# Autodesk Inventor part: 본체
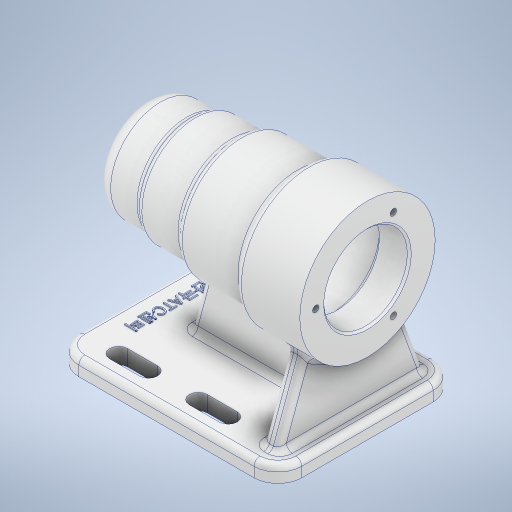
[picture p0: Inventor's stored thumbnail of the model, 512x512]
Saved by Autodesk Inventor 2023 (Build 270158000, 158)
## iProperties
Created: 2022-07
Part Number: 본체
Material: 알루미늄 6061
Document SubType Name: Modeling
Designer: owner
Density: 2.7 g/cm^3
Appearance: 알루미늄 - 평지
Mass: 693.1 g
Surface Area: 698.776 cm^2
Volume: 256.704 cm^3
Author: owner
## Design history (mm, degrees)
sketch "스케치1"
  geometry: L1 (44, -45)-(-44, -45); L2 (-56, -33)-(-56, 33); L3 (-44, 45)-(44, 45); L4 (56, 33)-(56, -33); L5 (56, -45)-(-56, 45); L6 (-56, -45)-(56, 45); A1 r 12 centre (44, 33) between (56, 33) and (44, 45); A2 r 12 centre (44, -33) between (44, -45) and (56, -33); A3 r 12 centre (-44, -33) between (-56, -33) and (-44, -45); A4 r 12 centre (-44, 33) between (-44, 45) and (-56, 33); 1 further point
  constraints: 12 end point, 8 point on circle, 8 point on line, 8 tangent, 4 centre point, 3 equal radius, 2 midpoint, 2 parallel, 1 horizontal, 1 perpendicular
  dimensions: "d0" = 112 distance between parallel lines of L2 L4; "d1" = 90 distance of L6.start L5.end; "d4" = 12 radius of A1
extrude "돌출1" new body sketch "스케치1" distance "d2" = 8; taper "d3" = 0 deg
sketch "스케치2"
  geometry: L1 (-36, -33)-(-21, -33); L2 (-36, -37.5)-(-21, -37.5); L3 (-21, -28.5)-(-36, -28.5); L4 (-56, 33)-(-56, -33) reference; L5 (-44, -45)-(44, -45) reference; L6 (19, -28.5)-(4, -28.5); L7 (4, -37.5)-(19, -37.5); L8 (-21, 37.5)-(-36, 37.5); L9 (-36, 28.5)-(-21, 28.5); L10 (19, 37.5)-(4, 37.5); L11 (4, 28.5)-(19, 28.5); A1 r 4.5 centre (-36, -33) between (-36, -28.5) and (-36, -37.5); A2 r 4.5 centre (-21, -33) between (-21, -37.5) and (-21, -28.5); A3 r 4.5 centre (19, -33) between (19, -37.5) and (19, -28.5); A4 r 4.5 centre (4, -33) between (4, -28.5) and (4, -37.5); A5 r 4.5 centre (-21, 33) between (-21, 28.5) and (-21, 37.5); A6 r 4.5 centre (-36, 33) between (-36, 37.5) and (-36, 28.5); A7 r 4.5 centre (19, 33) between (19, 28.5) and (19, 37.5); A8 r 4.5 centre (4, 33) between (4, 37.5) and (4, 28.5); 2 further points
  constraints: 20 end point, 16 point on circle, 8 centre point, 4 tangent, 2 horizontal, 1 midpoint, 1 parallel, 1 vertical, 30 other
  dimensions: "d5" = 15 distance of L1.start L1.end; "d6" = 9 diameter of A2; "d7" = 20 distance from line of L1.start L4; "d8" = 33 distance from line of L1 point (0, 0); "d11" = 40 distance of L1.end A3.centre; "d14" = 66 distance of L1.end A5.centre
extrude "돌출2" cut sketch "스케치2" stored distance "d17" = 8; taper "d18" = 0 deg
fillet "모깎기1" dims "d19" = 3
sketch "스케치3"
  geometry: L1 (-56, 33)-(-56, -33) reference; 2 further points
  constraints: 1 horizontal alignment, 1 other
  dimensions: "d20" = 12 distance from line of point (-44, 0) L1
feature "엠보싱1" sketch "스케치3" dims "d0" = 112, "d1" = 90, "d4" = 12, "d21" = 0.5, "d22" = 0
sketch "스케치4"
  geometry: L1 (-56, 70)-(56, 70); L2 (-44, 0)-(44, 0) reference; L3 (-47, 80.5)-(-47, 85.7); L4 (-46.7, 86)-(-43, 86); L5 (-43, 86)-(-43, 87.2); L6 (-42.7, 87.5)-(-25, 87.5); L7 (-25, 87.5)-(-25, 90.7); L8 (-24.7, 91)-(-13, 91); L9 (-13, 91)-(-13, 91); L10 (-10, 94)-(38, 94); L11 (41, 91)-(41, 91); L12 (41, 91)-(55, 91); L13 (56, 104)-(56, 92); L14 (-56, 87)-(-56, 70); L15 (-48, 95)-(-32, 95); L16 (-32, 95)-(-32, 97); L17 (-32, 97)-(-10, 97); L18 (-10, 97)-(-10, 100); L19 (-10, 100)-(24, 100); L20 (24, 100)-(24, 104); L21 (24, 104)-(56, 104); L22 (-47, 80.5)-(-47, 80.5); L23 (-50, 77.5)-(-50, 70); L24 (56, 0)-(56, 5) reference; L25 (55, 91)-(56, 92); A1 r 8 centre (-48, 87) between (-48, 95) and (-56, 87); A2 r 3 centre (-47, 77.5) between (-47, 80.5) and (-50, 77.5); A3 r 3 centre (-10, 91) between (-10, 94) and (-13, 91); A4 r 3 centre (38, 91) between (41, 91) and (38, 94); A5 r 0.3 centre (-46.7, 85.7) between (-46.7, 86) and (-47, 85.7); A6 r 0.3 centre (-42.7, 87.2) between (-42.7, 87.5) and (-43, 87.2); A7 r 0.3 centre (-24.7, 90.7) between (-24.7, 91) and (-25, 90.7); 7 further points
  constraints: 46 end point, 17 perpendicular, 14 point on circle, 14 tangent, 8 point on line, 7 centre point, 4 equal radius, 3 horizontal, 2 collinear, 1 vertical
  dimensions: "d23" = 70 distance between parallel lines of L1 L2; "d24" = 112 distance between parallel lines of L13 L14; "d28" = 42 diameter of L8 L1; "d29" = 48 diameter of L10 L1; "d36" = 4 distance between parallel lines of L5 L3; "d37" = 18 distance between parallel lines of L7 L5; "d38" = 12 distance between parallel lines of L9 L7; "d39" = 54 distance between parallel lines of L11 L9; "d40" = 3 distance of L3.start point (-50, 80.5); "d41" = 15 distance between parallel lines of L13 L11; "d42" = 21 diameter of L22 L1; "d43" = 32 diameter of L4 L1; "d44" = 35 diameter of L6 L1; "d45" = 50 diameter of L15 L1; "d46" = 54 diameter of L17 L1; "d47" = 60 diameter of L19 L1; "d48" = 24 distance between parallel lines of L14 L16; "d49" = 46 distance between parallel lines of L18 L14; "d50" = 80 distance between parallel lines of L14 L20; "d51" = 68 diameter of L21 L1; "d52" = 8 radius of A1; "d53" = 3 radius of A2; "d54" = 1 distance of L12.end point (56, 91); "d55" = 1 distance of L13.end point (56, 91) (= d54); "d56" = 0.3 radius of A5
revolve "회전1" sketch "스케치4" stored, may be unused: angle "d57" = 90 deg
fillet "모깎기2" dims "d58" = 3
sketch "스케치5" dims "d59" = 52
  geometry: C1 r 15.7 at (0, 0) reference; C2 r 2 at (-26, 0); 2 further points
  constraints: 2 horizontal alignment, 1 centre point, 1 coincident, 2 other
  dimensions: "d60" = 4 diameter of C2
hole "구멍1" sketch "스케치5" at (-26, 0) diameter "d61" = 3.242; stored, may be unused: countersink angle "d65" = 90 deg, drill point angle "d67" = 118 deg; dims "d62" = 8, "d63" = 4, "d64" = 2, "d66" = 11
node "작업 평면1"
sketch "스케치6"
  geometry: L1 (9.591, 45.342)-(-4, 8); L2 (56.409, 45.342)-(70, 8); L3 (-12, 0)-(-12, 5) reference; L4 (0, 8)-(66, 8) reference; L5 (-9, 8)-(0, 8) reference; L6 (66, 8)-(75, 8) reference; L7 (78, 0)-(78, 5) reference; A1 r 34 centre (33, 70) between (9.591, 45.342) and (56.409, 45.342) reference; 1 further point
  constraints: 4 end point, 2 point on circle, 2 point on line
  dimensions: "d72" = 8 distance from line of L1.end L3; "d73" = 110 deg angle of L1 L5; "d74" = 110 deg angle of L2 L6; "d75" = 8 distance from line of L2.end L7
extrude "돌출3" join sketch "스케치6" distance "d76" = 8; taper "d77" = 0 deg
sketch "스케치7"
  geometry: L1 (-19.622, 43)-(-29, 8); L2 (48, 8)-(48, 45.342) reference; L3 (-30.356, 43)-(-12.196, 43) reference; L4 (-7, 40)-(21, 40) reference; L5 (26.657, 36)-(56, 36) reference; L6 (40, 45.342)-(40, 8) reference; L7 (-44, 8)-(44, 8) reference; A1 r 3 centre (-12.196, 40) between (-9.598, 41.5) and (-12.196, 43) reference; A2 r 3 centre (-7, 43) between (-9.598, 41.5) and (-7, 40) reference; A3 r 3 centre (21, 37) between (23.828, 38) and (21, 40) reference; A4 r 3 centre (26.657, 39) between (23.828, 38) and (26.657, 36) reference; 1 further point
  constraints: 2 end point, 2 point on line
  dimensions: "d78" = 77 distance from line of L2 L1.end; "d80" = 105 deg angle of L1 L7
feature "리브1" sketch "스케치7" dims "d81" = 1, "d82" = 8, "d83" = 0, "d84" = 0, "d85" = 1, "d86" = 1
fillet "모깎기3" dims "d87" = 3
fillet "모깎기4" dims "d88" = 3
node "솔리드1"
pattern_circular "원형 패턴1" dims angle "d69" = 360 deg
feature "A9D066F2-1C7D-4E18-AEED-F7BC21143FA4" dims "d61" = 3.242, "d62" = 8, "d63" = 4, "d64" = 2, "d65" = 90 deg, "d66" = 11, "d67" = 118 deg
other parameters: "d71" = -8
